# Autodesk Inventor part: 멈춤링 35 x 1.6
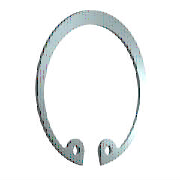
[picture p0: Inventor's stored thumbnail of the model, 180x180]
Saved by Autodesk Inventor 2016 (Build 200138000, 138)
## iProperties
IsCustomPart: 1
Created: 2012-02
Part Number: 멈춤링 35 x 1.6
Material: 강철, 연강
Description: 리테이닝 링(C형)
Document SubType Name: Modeling
Standard: KS B 1336
Designer: mduedu
Standards Organization: KS
Language: ko-KR
Size Designation: 35x1.6
Categories: <MemberInstance><Categories><Category DisplayName="샤프트 부품" InternalName="7f7aeb1f-a693-4053-b835-cee3144e0d98" Mnemonic="SHFT"><Category DisplayName="써클립" Inter
Density: 1 g/cm^3
Appearance: 파란색 - 벽 페인트 - 광택
Author: mduedu
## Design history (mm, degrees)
sketch "스케치1"
  geometry: L1 (0, 15.113)-(0, -73.177) reference; L2 (-45.5, 0)-(45.5, 0) reference; L3 (-4.964, 1)-(1.502, 1); L4 (0, -2.5)-(-5.307, -2.5); L5 (0, -17.5)-(-8.583, -33.888); L6 (-8.583, -33.888)-(-21.772, -26.981); L7 (-7.377, -31.585)-(-17.631, -26.214); L8 (-5.162, -32.745)-(-6.29, -34.898); L9 (5.162, -32.745)-(6.29, -34.898); C1 r 1.25 at (-7.377, -31.585); C2 r 1.25 at (7.377, -31.585); A1 r 15.875 centre (0, -18.375) between (11.82, -28.972) and (-11.82, -28.972); A2 r 18.5 centre (0, -17.5) between (6.29, -34.898) and (-6.29, -34.898); A3 r 2.5 centre (-7.377, -31.585) between (-5.162, -32.745) and (-8.668, -29.444); A4 r 2.5 centre (-9.959, -27.303) between (-11.82, -28.972) and (-8.668, -29.444); A5 r 2.5 centre (9.959, -27.303) between (8.668, -29.444) and (11.82, -28.972); A6 r 2.5 centre (7.377, -31.585) between (8.668, -29.444) and (5.162, -32.745); 3 further points
  constraints: 15 point on circle, 14 end point, 9 symmetric about line, 8 centre point, 6 tangent, 4 coincident, 4 point on line, 3 perpendicular, 1 parallel, 4 other
  dimensions: "d8" = 0.875 distance of A1.centre L5.start (= 0.25 x SRB1); "d38" = 3.5 distance between parallel lines of L4 L3 (= SRB1); "d39" = 17.5 distance from line of L5.start L2 (= 0.5 x WD); "d43" = 18.5 radius of A2 (= 0.5 x ND); "d45" = 2.6 distance between parallel lines of L7 L6 (= 0.5 x SRB2); "d46" = 2.5 radius of A4 (= SD5); "d47" = 6.29 distance from line of L1 L8.end (= 0.17 x ND); "d48" = 2.5 diameter of C1 (= SD5); "d49" = 2.5 radius of A3 (= SD5)
extrude "본체" new body sketch "스케치1" distance "d2" = 1.6 (= SD); taper "d3" = 0 deg
workaxis "Work Axis1"
workaxis "Work Axis2"
workplane "Work Plane1"
body "Solid1"
other parameters: "WD" = 35 [user parameter; used in 3 equation terms], "SD" = 1.6 [user parameter; used in 1 equation term], "SRB1" = 3.5 [user parameter; used in 2 equation terms], "ND" = 37 [user parameter; used in 2 equation terms], "SRB2" = 5.2 [user parameter; used in 1 equation term], "SD5" = 2.5 [user parameter; used in 3 equation terms], "d50" = 0, "d51" = 0, "d52" = 0, "d53" = 0, "WDMIN" = 34 [user parameter], "SD6" = 37.8 [user parameter], "WDMAX" = 35 (= WD) [user parameter], "NND" = 35 (= WD) [user parameter]
